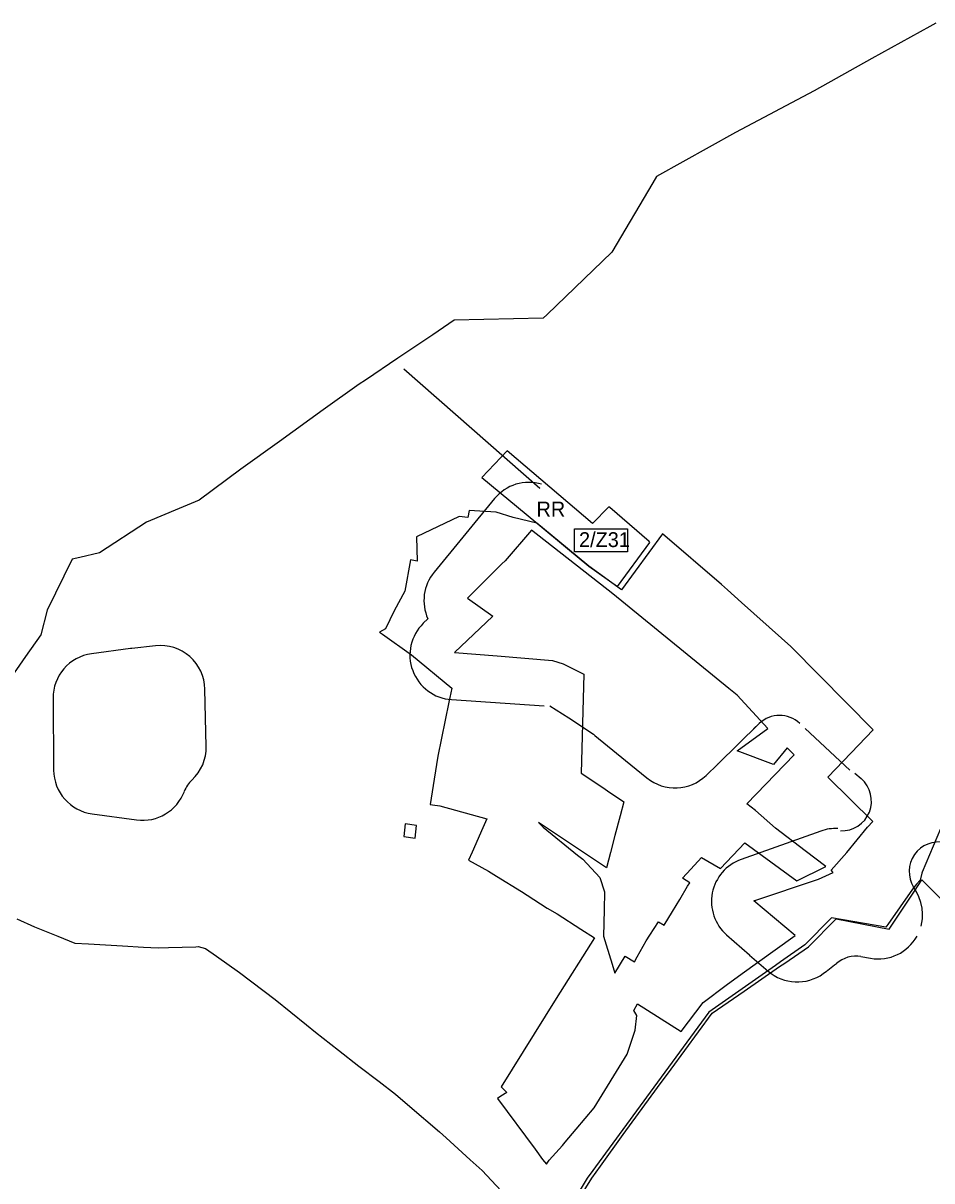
# Model space of a CAD drawing. Extents: x -445049 to -440454, y -1148980 to -1129741.
# Drawn here: x -443200 to -442589, y -1130999 to -1130220 of the extents above; entities that cross this region are included whole.
import ezdxf

# ---------------------------------------------------------------- set-up
doc = ezdxf.new("R2010")
doc.units = 0
for name, color, linetype in [('Vrstva 12', 7, 'Continuous'), ('Vrstva 23', 7, 'Continuous'), ('Vrstva 3', 7, 'Continuous'), ('Vrstva 4', 7, 'Continuous'), ('Vrstva 5', 7, 'Continuous'), ('Vrstva 7', 7, 'Continuous'), ('Vrstva 8', 7, 'Continuous')]:
    doc.layers.add(name, color=color, linetype=linetype)

msp = doc.modelspace()

# ---------------------------------------------------------------- linework, layer by layer
at = {"layer": 'Vrstva 12'}
msp.add_lwpolyline([(-442830.79, -1131018.44), (-442817.54, -1130997.27), (-442811.68, -1130989.14), (-442796.36, -1130967.88), (-442773.25, -1130936.1), (-442764.06, -1130923.79), (-442736.54, -1130886.23), (-442714.95, -1130871.33), (-442691.08, -1130854.76), (-442687.58, -1130852.48), (-442671.58, -1130841.36), (-442652.99, -1130822.57), (-442617.39, -1130829.63), (-442600.38, -1130804.06), (-442595.33, -1130796.33), (-442567.97, -1130823.69)], dxfattribs=at)
at = {"layer": 'Vrstva 23'}
for p, q in [((-442944.04, -1130452.35), (-442852.55, -1130532.73)), ((-442859.89, -1130526.28), (-442852.39, -1130532.88)), ((-442882.93, -1130539.73), (-442923.67, -1130589.27)), ((-442927.85, -1130620.67), (-442930.92, -1130623.68)), ((-443128.04, -1130640.65), (-443154.16, -1130644.2)), ((-443111.09, -1130638.82), (-443127.18, -1130640.54)), ((-443180.11, -1130674.18), (-443179.71, -1130722.48)), ((-443077.05, -1130706.51), (-443077.92, -1130667.98)), ((-442911.91, -1130675.04), (-442849.56, -1130679.17)), ((-442732.5, -1130718.28), (-442705.38, -1130691.66)), ((-442708.76, -1130694.82), (-442704.9, -1130691.17)), ((-442673.82, -1130694.57), (-442643.92, -1130722.65)), ((-442815.51, -1130699.11), (-442794.77, -1130716.01)), ((-442794.77, -1130716.01), (-442780.37, -1130727.75)), ((-442740.58, -1130726.08), (-442732.68, -1130718.45)), ((-442640.45, -1130724.62), (-442636.23, -1130728.26)), ((-443153.75, -1130751.95), (-443123.88, -1130756.01)), ((-442663.35, -1130763.52), (-442716.99, -1130782.63)), ((-442726.75, -1130833.41), (-442711.47, -1130846.87)), ((-442711.31, -1130847.01), (-442698.91, -1130857.77)), ((-442658.64, -1130857.22), (-442654.11, -1130853.69)), ((-442636.34, -1130848.07), (-442629.91, -1130849.18)), ((-442661.74, -1130859.48), (-442659.59, -1130857.93))]:
    msp.add_line(p, q, dxfattribs=at)
for points in [[(-442845.78, -1130679.21), (-442832.9, -1130687.33), (-442816.28, -1130698.4)], [(-442595.89, -1130827.48), (-442594.93, -1130822.58), (-442594.86, -1130819.23), (-442595.16, -1130815.5), (-442596.02, -1130811.57), (-442597.34, -1130807.78), (-442599.07, -1130804.35), (-442600.97, -1130801.27)]]:
    msp.add_lwpolyline(points, dxfattribs=at)
for centre, radius, start, end in [((-442859.76, -1130558.79), 30, 73.54913, 140.56344), ((-442900.5, -1130608.33), 30, 140.56344, 204.28443), ((-442909.93, -1130645.11), 30, 134.40204, 266.21032), ((-443150.11, -1130673.93), 30, 97.7537, 180.48193), ((-443123.99, -1130670.37), 30, 96.09339, 97.7537), ((-443107.91, -1130668.65), 30, 1.28935, 96.09339), ((-442691.17, -1130705.71), 20, 46.802, 133.36055), ((-442828.14, -1130714.61), 20, 50.81536, 56.6948), ((-443107.04, -1130707.18), 30, 312.88626, 1.28935), ((-442775.82, -1130692.76), 30, 230.81536, 230.82081), ((-442753.52, -1130696.86), 30, 313.98405, 314.46034), ((-443149.71, -1130722.22), 30, 180.48193, 262.26159), ((-443073.02, -1130743.82), 20, 132.88626, 159.46901), ((-442761.42, -1130704.49), 30, 230.82081, 313.98404), ((-442649.3, -1130743.4), 20, 267.74497, 49.20099), ((-443119.84, -1130726.28), 30, 262.26159, 339.46901), ((-442653.28, -1130791.78), 30, 87.29366, 109.61073), ((-442583.92, -1130790.81), 20, 78.7334, 211.51649), ((-442706.93, -1130810.89), 30, 109.61073, 228.62796), ((-442624.78, -1130819.62), 30, 260.16108, 330.91745), ((-442691.64, -1130824.35), 30, 228.62796, 229.0372), ((-442672.56, -1130830.04), 30, 307.96037, 310.99839), ((-442639.76, -1130867.77), 20, 80.16108, 130.99839), ((-442679.25, -1130835.12), 30, 229.0372, 305.70455), ((-442677.09, -1130833.57), 30, 305.70455, 307.96037)]:
    msp.add_arc(centre, radius, start, end, dxfattribs=at)
at = {"layer": 'Vrstva 3'}
msp.add_lwpolyline([(-442829.26, -1130560.13), (-442793.42, -1130560.13), (-442793.42, -1130575.53), (-442829.26, -1130575.53)], close=True, dxfattribs=at)
at = {"layer": 'Vrstva 5'}
for points in [[(-442586.03, -1130219.67), (-442590.09, -1130221.92), (-442629.02, -1130243.57), (-442667.94, -1130265.22), (-442720.69, -1130293.35), (-442774.04, -1130323.01), (-442776.45, -1130327.08), (-442804.09, -1130373.76), (-442847.63, -1130415.89), (-442850.14, -1130418.32), (-442910.05, -1130419.7), (-442924.6, -1130429.5), (-442948.01, -1130445.26), (-442969.91, -1130460), (-442974.07, -1130462.8), (-442998.28, -1130479.96), (-443027.65, -1130501.18), (-443053.63, -1130519.95), (-443081.71, -1130540.83), (-443095.23, -1130546.49), (-443117.23, -1130555.7), (-443148.93, -1130576.18), (-443161.99, -1130579.3), (-443167.28, -1130580.57), (-443184.16, -1130614.88), (-443188.44, -1130631.49), (-443198.69, -1130646.13), (-443231.83, -1130693.59)], [(-443204.51, -1130822.59), (-443192.7, -1130828.08), (-443176.89, -1130834.39), (-443165.45, -1130838.96), (-443156.14, -1130839.47), (-443133.41, -1130840.86), (-443119.22, -1130841.72), (-443109.42, -1130842.03), (-443102.37, -1130841.84), (-443084.12, -1130841.36), (-443082.38, -1130841.31), (-443077.41, -1130842.52), (-443070.13, -1130847.71), (-443054.57, -1130858.81), (-443030.66, -1130876.94), (-443009.46, -1130894.01), (-443003.41, -1130898.87), (-442988, -1130911.01), (-442974.22, -1130921.83), (-442960.65, -1130932.13), (-442949.68, -1130940.64), (-442940.07, -1130948.87), (-442919.98, -1130966.06), (-442915.59, -1130970.05), (-442899.33, -1130984.82), (-442891.39, -1130992.04), (-442872.21, -1131012.5)]]:
    msp.add_lwpolyline(points, dxfattribs=at)
at = {"layer": 'Vrstva 7'}
for points in [[(-442943.33, -1130602.13), (-442950.5, -1130615.31), (-442956.43, -1130627.36), (-442960.34, -1130629.7), (-442958.36, -1130631.07), (-442938.76, -1130644.95), (-442911.75, -1130667.29), (-442913.7, -1130676.76), (-442921.15, -1130713.06), (-442923.53, -1130728.6), (-442926.23, -1130745.65), (-442924.67, -1130745.89), (-442919.73, -1130746.65), (-442888.21, -1130755.34), (-442890.85, -1130761.31), (-442898.06, -1130777.63), (-442900.51, -1130783.18), (-442886.95, -1130790.6), (-442881.6, -1130793.91), (-442864.79, -1130804.31), (-442861.04, -1130806.73), (-442847.59, -1130815.4), (-442840.85, -1130819.31), (-442824.94, -1130829.54), (-442815.8, -1130835.42), (-442815.8, -1130835.42), (-442841.41, -1130876.33), (-442878.56, -1130935.7), (-442874.76, -1130939.49), (-442878.66, -1130942.05), (-442881.05, -1130943.62), (-442855.7, -1130977.68), (-442850.7, -1130984.61), (-442848.03, -1130987.74), (-442846.26, -1130985.08), (-442837.31, -1130975.19), (-442835.4, -1130972.93), (-442827.97, -1130964.15), (-442815.97, -1130949.95), (-442793.77, -1130913.74), (-442791.71, -1130907.68), (-442788.25, -1130897.47), (-442787.22, -1130887.73), (-442789.28, -1130884.24), (-442786.69, -1130879.87), (-442757.3, -1130898.53), (-442742.59, -1130878.85), (-442727.17, -1130867.22), (-442716.25, -1130859.47), (-442705.91, -1130852.03), (-442680.62, -1130833.84), (-442708.39, -1130810.49), (-442664.85, -1130795.84), (-442655.04, -1130791.32), (-442656.49, -1130789.84), (-442645.83, -1130777.91), (-442631.95, -1130760.85), (-442628.3, -1130756.99), (-442658.56, -1130727.23), (-442642.91, -1130710.91), (-442628.11, -1130695.47), (-442664.18, -1130658.76), (-442683.57, -1130639.32), (-442689.8, -1130633.74), (-442716.77, -1130609.61), (-442726.15, -1130601.22), (-442730.28, -1130597.57), (-442769.84, -1130563.37), (-442797.48, -1130601.17), (-442819.59, -1130585.31), (-442833.94, -1130573.34), (-442854.46, -1130556.23), (-442870.4, -1130552.34), (-442881.83, -1130548.8), (-442899.94, -1130547.77), (-442900.89, -1130552.4), (-442906.83, -1130551.85), (-442935.59, -1130565.51), (-442934.95, -1130581.95), (-442939.51, -1130581.05)], [(-442935.41, -1130759.68), (-442943.05, -1130758.76), (-442944.08, -1130767.3), (-442936.44, -1130768.22)]]:
    msp.add_lwpolyline(points, close=True, dxfattribs=at)
for points in [[(-442857.99, -1130561.05), (-442875.83, -1130581.54), (-442877.95, -1130583.62), (-442888.71, -1130594.21), (-442892.81, -1130598.35), (-442901.11, -1130606.66), (-442884.23, -1130618.77), (-442909.95, -1130643.38), (-442881.22, -1130645.68), (-442844.02, -1130648.65), (-442836.87, -1130651.05), (-442822.81, -1130658.01), (-442824.73, -1130724.51), (-442810.04, -1130734.31), (-442806.91, -1130736.4), (-442796.04, -1130743.88), (-442798.49, -1130753.32), (-442801.9, -1130766.46), (-442804.9, -1130778.02), (-442807.56, -1130788.24), (-442853.44, -1130757.82), (-442850.33, -1130760.85), (-442827.14, -1130779.66)], [(-442827.14, -1130779.66), (-442823.52, -1130782.56), (-442812.02, -1130794.84), (-442809.03, -1130804.54), (-442809.27, -1130816.45), (-442809.64, -1130834.24), (-442807.84, -1130840.23), (-442803.74, -1130853.21), (-442802.06, -1130859.13), (-442794.95, -1130847.86), (-442788.77, -1130851.52), (-442786.96, -1130848.31), (-442780.84, -1130837.45), (-442778.39, -1130833.62), (-442772.61, -1130824.55), (-442768.86, -1130826.87), (-442763.26, -1130817.61), (-442758.36, -1130809.5), (-442753.02, -1130800.68), (-442751.61, -1130798.35), (-442756.57, -1130795.29), (-442750.96, -1130789.28), (-442743.58, -1130781.36), (-442730.78, -1130788.7), (-442714.55, -1130771.46), (-442679.52, -1130797.05), (-442659.97, -1130787.46), (-442673.81, -1130776.9), (-442693.81, -1130761.63), (-442707.35, -1130749.79), (-442713.2, -1130745.14), (-442681.3, -1130712.13), (-442685.95, -1130707.52), (-442695.31, -1130718.74), (-442719.59, -1130709.52), (-442699.07, -1130694.44), (-442719.7, -1130672.12), (-442725.17, -1130667.65), (-442803.29, -1130603.73), (-442857.99, -1130561.05)], [(-442577.91, -1130750.47), (-442595.19, -1130791.2), (-442595.44, -1130791.82), (-442596.58, -1130796.51), (-442598.93, -1130799.33), (-442601.75, -1130802.71), (-442618.38, -1130826.48), (-442619.6, -1130828.22), (-442656.08, -1130821.98), (-442674.2, -1130840.11), (-442690.42, -1130851.51), (-442693.92, -1130853.97), (-442738.78, -1130885.49), (-442775.83, -1130936), (-442815.11, -1130989.54), (-442816.88, -1130991.96), (-442820.71, -1130997.18), (-442833.2, -1131018.12)]]:
    msp.add_lwpolyline(points, dxfattribs=at)
at = {"layer": 'Vrstva 8'}
msp.add_lwpolyline([(-442805.4, -1130545.82), (-442805.94, -1130545.34), (-442817.02, -1130556.42), (-442874.56, -1130507.6), (-442891.42, -1130525.43), (-442855.24, -1130555.59), (-442833.94, -1130573.34), (-442819.59, -1130585.31), (-442800.13, -1130599), (-442778.37, -1130569.2), (-442779, -1130568.66), (-442805.4, -1130545.82)], dxfattribs=at)

# ---------------------------------------------------------------- texts
at = {"layer": 'Vrstva 3'}
msp.add_text('2/Z31', height=10, dxfattribs=at).set_placement((-442826.09, -1130572.35))
at = {"layer": 'Vrstva 4'}
msp.add_text('RR', height=10, dxfattribs=at).set_placement((-442854.71, -1130551.78))

doc.saveas('drawing.dxf')
